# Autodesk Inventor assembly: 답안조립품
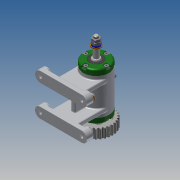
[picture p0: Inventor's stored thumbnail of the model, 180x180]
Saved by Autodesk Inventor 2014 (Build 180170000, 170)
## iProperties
Created: 2015-11
Part Number: 답안조립품
Document SubType Name: Assembly
Designer: 12
Author: 12
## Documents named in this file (16)
- C:\Users\12\Desktop\451110V1046\답안조립품.iam
- C:\Users\12\Desktop\451110V1046\본체.ipt
- C:\Users\12\Desktop\451110V1046\V벨트풀리.ipt
- C:\Users\12\Desktop\451110V1046\축.ipt
- C:\Users\12\Desktop\451110V1046\스퍼기어.ipt
- C:\Users\12\Desktop\451110V1046\키 3 x 3 x 12.ipt
- C:\Users\12\Desktop\451110V1046\베어링 15 x 32 x 9.ipt
- C:\Users\12\Desktop\451110V1046\커버.ipt
- C:\Users\12\Desktop\451110V1046\스프링와셔 8.ipt
- C:\Users\12\Desktop\451110V1046\와셔 8x17.ipt
- C:\Users\12\Desktop\451110V1046\너트 M 8.ipt
- C:\Users\12\Desktop\451110V1046\오일 실 15 25 7.ipt
- C:\Users\12\Desktop\451110V1046\볼트 M4 x 12.ipt
- C:\Users\12\Desktop\451110V1046\볼트 M 6 x 8.ipt
- C:\Users\12\Desktop\451110V1046\와셔 6x11.5.ipt
- C:\Users\12\Desktop\451110V1046\니플 M 6 x 0.75.ipt
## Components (11 placed, 3 different names)
1. V벨트풀리:1
2. KS B 2023 6002 - 15 x 32 x 9:1
3. KS B 2023 6002 - 15 x 32 x 9:2
4. ISO 4762 M4 x 12:5
5. ISO 4762 M4 x 12:6
6. ISO 4762 M4 x 12:7
7. ISO 4762 M4 x 12:8
8. ISO 4762 M4 x 12:1
9. ISO 4762 M4 x 12:2
10. ISO 4762 M4 x 12:3
11. ISO 4762 M4 x 12:4
